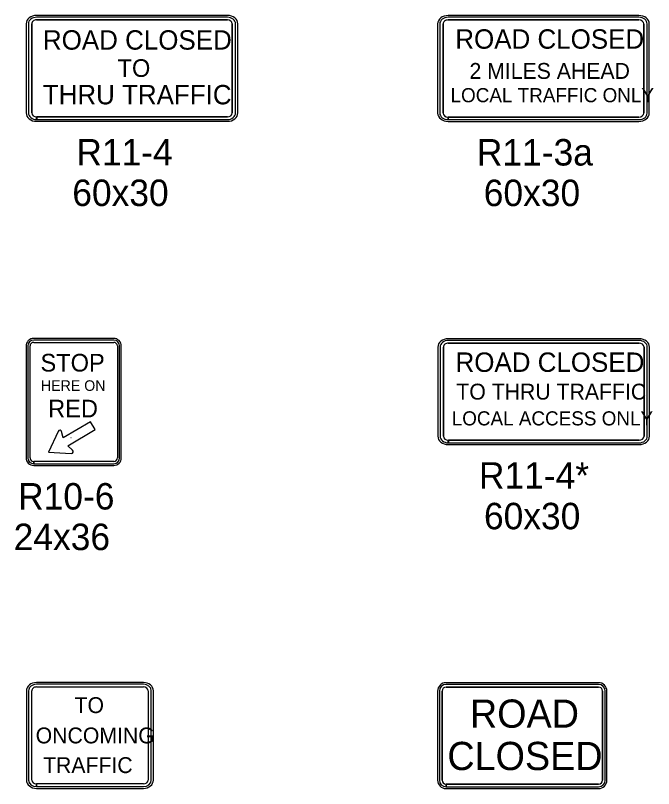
# Model space of a CAD drawing. Extents: x 1458 to 4498, y 17709 to 24109.
# Drawn here: x 3209.5 to 3571.1, y 20904.5 to 21342.5 of the extents above; entities that cross this region are included whole.
import ezdxf

# ---------------------------------------------------------------- set-up
doc = ezdxf.new("R2010")
doc.units = 0
doc.layers.add('P_TRAF_TCP_General', color=7, linetype='Continuous')

msp = doc.modelspace()

# ---------------------------------------------------------------- linework, layer by layer
at = {"layer": 'P_TRAF_TCP_General'}
for p, q in [((3329.57, 21342.46), (3221.49, 21342.46)), ((3562.76, 21342.41), (3454.67, 21342.41)), ((3215.56, 21337.71), (3215.56, 21287.23)), ((3216.81, 21337.71), (3216.81, 21287.23)), ((3218.68, 21337.71), (3218.68, 21287.23)), ((3218.68, 21287.23), (3218.68, 21337.71)), ((3329.57, 21341.46), (3221.49, 21341.46)), ((3329.57, 21339.96), (3221.49, 21339.96)), ((3221.49, 21339.96), (3329.57, 21339.96)), ((3332.38, 21287.23), (3332.38, 21337.71)), ((3332.38, 21337.71), (3332.38, 21287.23)), ((3334.26, 21287.23), (3334.26, 21337.71)), ((3335.51, 21287.23), (3335.51, 21337.71)), ((3448.74, 21337.66), (3448.74, 21287.18)), ((3449.99, 21337.66), (3449.99, 21287.18)), ((3451.86, 21337.66), (3451.86, 21287.18)), ((3451.86, 21287.18), (3451.86, 21337.66)), ((3562.76, 21341.41), (3454.67, 21341.41)), ((3562.76, 21339.91), (3454.67, 21339.91)), ((3454.67, 21339.91), (3562.76, 21339.91)), ((3565.57, 21287.18), (3565.57, 21337.66)), ((3565.57, 21337.66), (3565.57, 21287.18)), ((3567.44, 21287.18), (3567.44, 21337.66)), ((3568.69, 21287.18), (3568.69, 21337.66)), ((3221.49, 21284.98), (3329.57, 21284.98)), ((3221.49, 21283.48), (3221.49, 21284.98)), ((3329.57, 21284.98), (3221.51, 21284.98)), ((3221.51, 21284.98), (3221.51, 21283.48)), ((3454.67, 21284.93), (3562.76, 21284.93)), ((3454.67, 21283.43), (3454.67, 21284.93)), ((3562.76, 21284.93), (3454.69, 21284.93)), ((3454.69, 21284.93), (3454.69, 21283.43)), ((3221.49, 21282.48), (3329.57, 21282.48)), ((3221.51, 21283.48), (3329.57, 21283.48)), ((3454.68, 21282.43), (3562.76, 21282.43)), ((3454.69, 21283.43), (3562.76, 21283.43)), ((3265.17, 21159.52), (3219.81, 21159.52)), ((3265.17, 21158.58), (3219.81, 21158.58)), ((3265.17, 21158.58), (3219.81, 21158.58)), ((3562.89, 21159.32), (3454.8, 21159.32)), ((3562.89, 21158.32), (3454.8, 21158.32)), ((3215.5, 21155.21), (3215.5, 21091.86)), ((3216.44, 21155.21), (3216.44, 21091.86)), ((3216.44, 21155.21), (3216.44, 21091.86)), ((3217.75, 21091.86), (3217.75, 21155.21)), ((3219.81, 21157.27), (3265.17, 21157.27)), ((3267.23, 21155.21), (3267.23, 21091.86)), ((3268.54, 21091.86), (3268.54, 21155.21)), ((3268.54, 21091.86), (3268.54, 21155.21)), ((3269.48, 21091.86), (3269.48, 21155.21)), ((3448.87, 21154.57), (3448.87, 21104.09)), ((3450.12, 21154.57), (3450.12, 21104.09)), ((3451.99, 21154.57), (3451.99, 21104.09)), ((3451.99, 21104.09), (3451.99, 21154.57)), ((3562.89, 21156.82), (3454.8, 21156.82)), ((3454.8, 21156.82), (3562.89, 21156.82)), ((3565.7, 21104.09), (3565.7, 21154.57)), ((3565.7, 21154.57), (3565.7, 21104.09)), ((3567.57, 21104.09), (3567.57, 21154.57)), ((3568.82, 21104.09), (3568.82, 21154.57)), ((3251.93, 21112.24), (3236.58, 21103.11)), ((3254.57, 21107.81), (3251.93, 21112.24)), ((3233.71, 21106.85), (3228.21, 21095.13)), ((3236.58, 21103.11), (3235.65, 21106.69)), ((3239.22, 21098.67), (3254.57, 21107.81)), ((3240.97, 21103.24), (3240.96, 21103.24)), ((3454.8, 21101.85), (3562.89, 21101.85)), ((3454.8, 21100.35), (3454.8, 21101.85)), ((3562.89, 21101.85), (3454.82, 21101.85)), ((3454.82, 21101.85), (3454.82, 21100.35)), ((3241.91, 21096.16), (3239.22, 21098.67)), ((3454.81, 21099.35), (3562.89, 21099.35)), ((3454.82, 21100.35), (3562.89, 21100.35)), ((3228.21, 21095.13), (3241.14, 21094.37)), ((3219.81, 21088.49), (3219.81, 21089.8)), ((3219.81, 21088.49), (3265.17, 21088.49)), ((3265.17, 21089.8), (3219.82, 21089.8)), ((3219.82, 21089.8), (3219.82, 21088.49)), ((3219.82, 21088.49), (3265.17, 21088.49)), ((3219.81, 21087.55), (3265.17, 21087.55)), ((3281.97, 20964.55), (3221.4, 20964.55)), ((3281.97, 20963.55), (3221.4, 20963.55)), ((3281.97, 20963.55), (3221.4, 20963.55)), ((3221.4, 20962.05), (3281.97, 20962.05)), ((3539.96, 20964.47), (3453.49, 20964.47)), ((3539.96, 20963.47), (3453.49, 20963.47)), ((3539.96, 20961.97), (3453.49, 20961.97)), ((3453.49, 20961.97), (3539.96, 20961.97)), ((3215.7, 20959.81), (3215.7, 20909.33)), ((3216.9, 20959.81), (3216.9, 20909.33)), ((3216.9, 20959.81), (3216.9, 20909.33)), ((3218.7, 20909.33), (3218.7, 20959.81)), ((3284.67, 20959.81), (3284.67, 20909.33)), ((3286.47, 20909.33), (3286.47, 20959.81)), ((3286.47, 20909.33), (3286.47, 20959.81)), ((3287.67, 20909.33), (3287.67, 20959.81)), ((3448.75, 20959.72), (3448.75, 20909.24)), ((3449.75, 20959.72), (3449.75, 20909.24)), ((3451.25, 20959.72), (3451.25, 20909.24)), ((3451.25, 20909.24), (3451.25, 20959.72)), ((3542.21, 20909.24), (3542.21, 20959.72)), ((3542.21, 20959.72), (3542.21, 20909.24)), ((3543.71, 20909.24), (3543.71, 20959.72)), ((3544.71, 20909.24), (3544.71, 20959.72)), ((3221.4, 20905.58), (3221.4, 20907.08)), ((3221.4, 20905.58), (3281.97, 20905.58)), ((3221.4, 20904.58), (3281.97, 20904.58)), ((3281.97, 20907.08), (3221.42, 20907.08)), ((3221.42, 20907.08), (3221.42, 20905.58)), ((3221.42, 20905.58), (3281.97, 20905.58)), ((3453.49, 20906.99), (3539.96, 20906.99)), ((3453.49, 20905.5), (3453.49, 20906.99)), ((3453.5, 20904.5), (3539.96, 20904.5)), ((3539.96, 20906.99), (3453.51, 20906.99)), ((3453.51, 20906.99), (3453.51, 20905.5)), ((3453.51, 20905.5), (3539.96, 20905.5))]:
    msp.add_line(p, q, dxfattribs=at)
for centre, radius, start, end in [((3219.81, 21155.21), 4.31, 90, 180), ((3219.81, 21155.21), 3.37, 90, 180), ((3219.81, 21155.21), 3.37, 90, 180), ((3265.17, 21155.21), 4.31, 0, 90), ((3265.17, 21155.21), 3.37, 0, 90), ((3265.17, 21155.21), 3.37, 0, 90), ((3219.81, 21155.21), 2.06, 90, 180), ((3265.17, 21155.21), 2.06, 0, 90), ((3234.65, 21106.41), 1.04, 16.0071, 154.8644), ((3241.2, 21095.41), 1.04, 266.6355, 46.9299), ((3219.81, 21091.86), 4.31, 180, 270), ((3219.81, 21091.86), 3.37, 180, 270), ((3219.81, 21091.86), 3.37, 180, 270), ((3219.81, 21091.86), 2.06, 180, 270), ((3265.17, 21091.86), 3.37, 270, 0), ((3265.17, 21091.86), 3.37, 270, 0), ((3265.17, 21091.86), 2.06, 270, 0), ((3265.17, 21091.86), 4.31, 270, 0), ((3453.49, 20959.72), 4.75, 90, 180), ((3453.49, 20959.72), 3.75, 90, 180), ((3453.49, 20959.72), 2.25, 90, 180), ((3453.49, 20959.72), 2.25, 90, 180), ((3539.96, 20959.72), 4.75, 0, 90), ((3539.96, 20959.72), 3.75, 0, 90), ((3539.96, 20959.72), 2.25, 0, 90), ((3539.96, 20959.72), 2.25, 0, 90), ((3453.49, 20909.24), 4.75, 180, 270), ((3453.49, 20909.24), 3.75, 180, 270), ((3453.49, 20909.24), 2.25, 180, 270), ((3453.49, 20909.24), 2.25, 180, 270), ((3539.96, 20909.24), 2.25, 270, 0), ((3539.96, 20909.24), 3.75, 270, 0), ((3539.96, 20909.24), 2.25, 270, 0), ((3539.96, 20909.24), 4.75, 270, 0)]:
    msp.add_arc(centre, radius, start, end, dxfattribs=at)
for centre, major_axis, ratio, start_param, end_param in [((3221.49, 21337.71), (5.94, 0), 0.8, 1.570796, 3.141593), ((3329.57, 21337.71), (5.94, 0), 0.8, 0, 1.570796), ((3454.67, 21337.66), (5.94, 0), 0.8, 1.570796, 3.141593), ((3562.76, 21337.66), (5.94, 0), 0.8, 0, 1.570796), ((3221.49, 21337.71), (4.69, 0), 0.8, 1.570796, 3.141593), ((3221.49, 21337.71), (2.81, 0), 0.8, 1.570796, 3.141593), ((3221.49, 21337.71), (2.81, 0), 0.8, 1.570796, 3.141593), ((3329.57, 21337.71), (4.69, 0), 0.8, 0, 1.570796), ((3329.57, 21337.71), (2.81, 0), 0.8, 0, 1.570796), ((3329.57, 21337.71), (2.81, 0), 0.8, 0, 1.570796), ((3454.67, 21337.66), (4.69, 0), 0.8, 1.570796, 3.141593), ((3454.67, 21337.66), (2.81, 0), 0.8, 1.570796, 3.141593), ((3454.67, 21337.66), (2.81, 0), 0.8, 1.570796, 3.141593), ((3562.76, 21337.66), (4.69, 0), 0.8, 0, 1.570796), ((3562.76, 21337.66), (2.81, 0), 0.8, 0, 1.570796), ((3562.76, 21337.66), (2.81, 0), 0.8, 0, 1.570796), ((3221.49, 21287.23), (5.94, 0), 0.8, 3.141593, 4.712389), ((3221.49, 21287.23), (4.69, 0), 0.8, 3.141593, 4.712389), ((3221.49, 21287.23), (2.81, 0), 0.8, 3.141593, 4.712389), ((3221.49, 21287.23), (2.81, 0), 0.8, 3.141593, 4.712389), ((3329.57, 21287.23), (2.81, 0), 0.8, 4.712389, 6.283185), ((3329.57, 21287.23), (4.69, 0), 0.8, 4.712389, 6.283185), ((3329.57, 21287.23), (2.81, 0), 0.8, 4.712389, 6.283185), ((3329.57, 21287.23), (5.94, 0), 0.8, 4.712389, 6.283185), ((3454.67, 21287.18), (5.94, 0), 0.8, 3.141593, 4.712389), ((3454.67, 21287.18), (4.69, 0), 0.8, 3.141593, 4.712389), ((3454.67, 21287.18), (2.81, 0), 0.8, 3.141593, 4.712389), ((3454.67, 21287.18), (2.81, 0), 0.8, 3.141593, 4.712389), ((3562.76, 21287.18), (2.81, 0), 0.8, 4.712389, 6.283185), ((3562.76, 21287.18), (4.69, 0), 0.8, 4.712389, 6.283185), ((3562.76, 21287.18), (2.81, 0), 0.8, 4.712389, 6.283185), ((3562.76, 21287.18), (5.94, 0), 0.8, 4.712389, 6.283185), ((3454.8, 21154.57), (5.94, 0), 0.8, 1.570796, 3.141593), ((3454.8, 21154.57), (4.69, 0), 0.8, 1.570796, 3.141593), ((3562.89, 21154.57), (5.94, 0), 0.8, 0, 1.570796), ((3562.89, 21154.57), (4.69, 0), 0.8, 0, 1.570796), ((3454.8, 21154.57), (2.81, 0), 0.8, 1.570796, 3.141593), ((3454.8, 21154.57), (2.81, 0), 0.8, 1.570796, 3.141593), ((3562.89, 21154.57), (2.81, 0), 0.8, 0, 1.570796), ((3562.89, 21154.57), (2.81, 0), 0.8, 0, 1.570796), ((3454.8, 21104.09), (5.94, 0), 0.8, 3.141593, 4.712389), ((3454.8, 21104.09), (4.69, 0), 0.8, 3.141593, 4.712389), ((3454.8, 21104.09), (2.81, 0), 0.8, 3.141593, 4.712389), ((3454.8, 21104.09), (2.81, 0), 0.8, 3.141593, 4.712389), ((3562.89, 21104.09), (2.81, 0), 0.8, 4.712389, 6.283185), ((3562.89, 21104.09), (4.69, 0), 0.8, 4.712389, 6.283185), ((3562.89, 21104.09), (2.81, 0), 0.8, 4.712389, 6.283185), ((3562.89, 21104.09), (5.94, 0), 0.8, 4.712389, 6.283185), ((3221.4, 20959.81), (5.7, 0), 0.833333, 1.570796, 3.141593), ((3221.4, 20959.81), (5.7, 0), 0.833333, 1.570796, 3.141593), ((3221.4, 20959.81), (4.5, 0), 0.833333, 1.570796, 3.141593), ((3221.4, 20959.81), (4.5, 0), 0.833333, 1.570796, 3.141593), ((3221.4, 20959.81), (2.7, 0), 0.833333, 1.570796, 3.141593), ((3281.97, 20959.81), (5.7, 0), 0.833333, 0, 1.570796), ((3281.97, 20959.81), (4.5, 0), 0.833333, 0, 1.570796), ((3281.97, 20959.81), (4.5, 0), 0.833333, 0, 1.570796), ((3281.97, 20959.81), (2.7, 0), 0.833333, 0, 1.570796), ((3221.4, 20909.33), (5.7, 0), 0.833333, 3.141593, 4.712389), ((3221.4, 20909.33), (4.5, 0), 0.833333, 3.141593, 4.712389), ((3221.4, 20909.33), (4.5, 0), 0.833333, 3.141593, 4.712389), ((3221.4, 20909.33), (2.7, 0), 0.833333, 3.141593, 4.712389), ((3281.97, 20909.33), (4.5, 0), 0.833333, 4.712389, 6.283185), ((3281.97, 20909.33), (4.5, 0), 0.833333, 4.712389, 6.283185), ((3281.97, 20909.33), (2.7, 0), 0.833333, 4.712389, 6.283185), ((3281.97, 20909.33), (5.7, 0), 0.833333, 4.712389, 6.283185)]:
    msp.add_ellipse(centre, major_axis=major_axis, ratio=ratio, start_param=start_param, end_param=end_param, dxfattribs=at)

# ---------------------------------------------------------------- texts
for s, height, p in [('ROAD CLOSED', 10.9956, (3225.06, 21323.09)), ('ROAD CLOSED', 10.9956, (3458.76, 21323.62)), ('TO', 9.996, (3267.36, 21307.66)), ('2 MILES AHEAD', 8.9964, (3466.79, 21306.53)), ('THRU TRAFFIC', 10.9956, (3224.98, 21292.1)), ('LOCAL TRAFFIC ONLY', 7.9968, (3456.07, 21293.3)), ('R11-4', 14.994, (3243.99, 21257.49)), ('R11-3a', 14.994, (3470.98, 21257.44)), ('60x30', 14.994, (3241.69, 21234.5)), ('60x30', 14.994, (3474.87, 21234.45)), ('STOP', 9.996, (3223.69, 21140.74)), ('ROAD CLOSED', 10.9956, (3458.89, 21140.54)), ('HERE ON', 5.998, (3223.95, 21129.78)), ('TO THRU TRAFFIC', 8.9964, (3459.35, 21124.84)), ('RED', 9.996, (3228.03, 21114.75)), ('LOCAL ACCESS ONLY', 7.9968, (3456.73, 21110.21)), ('R11-4*', 14.994, (3472.15, 21074.36)), ('R10-6', 14.994, (3210.98, 21062.56)), ('60x30', 14.994, (3475, 21051.37)), ('24x36', 14.994, (3208.48, 21039.57)), ('TO', 8.996, (3242.96, 20947.24)), ('ROAD', 15.994, (3467.06, 20938.94)), ('ONCOMING', 8.996, (3220.94, 20930.07)), ('CLOSED', 15.994, (3454.25, 20914.95)), ('TRAFFIC', 8.996, (3225.12, 20913.26))]:
    msp.add_text(s, height=height, dxfattribs=at).set_placement(p)

doc.saveas('drawing.dxf')
